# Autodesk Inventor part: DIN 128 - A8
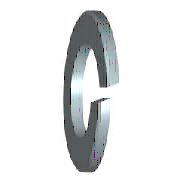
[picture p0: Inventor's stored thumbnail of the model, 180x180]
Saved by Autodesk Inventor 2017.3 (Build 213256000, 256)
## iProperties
Created: 2016-02
Part Number: DIN 128 - A8
Material: Acier, doux
Description: Rondelle élastique
Document SubType Name: Modeling
Standard: DIN 128
Designer: TJ
Standard Revision: 1994
Standards Organization: DIN
Language: fr-FR
Size Designation: A8
Categories: <MemberInstance><Categories><Category DisplayName="Visserie" InternalName="e4da775c-781d-43d5-af7c-5136215cf5a6" Mnemonic="FSTN"><Category DisplayName="Rondelle
Density: 7.85 g/cm^3
Appearance: Semi-poli
IsCustomPart: 0
Author: TJ
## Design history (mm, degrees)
sketch "Esquisse1"
  geometry: C1 r 7.4 at (0, 0); C2 r 4.25 at (0, 0); 1 further point
  constraints: 2 centre point, 2 coincident
  dimensions: "d0" = 8.5 diameter of C2 (= SD1); "d1" = 14.8 diameter of C1 (= SD2)
extrude "Corps" new body sketch "Esquisse1" distance "d2" = 1.6 (= SD); taper "d3" = 0 deg
sketch "Esquisse2"
  geometry: L1 (0, -4.25)-(0, 4.25) reference; L2 (1.6, 7.4)-(1.6, -7.4) reference; L3 (-1.2, 0)-(7.2, 0) reference; L4 (0, -0.32)-(1.6, 0.604); L5 (0, 0.32)-(1.6, 1.244)
  constraints: 4 end point, 4 point on line, 1 parallel
  dimensions: "d4" = 0.32 distance from line of L3 L4.start (= 0.2 x SD); "d5" = 0.32 distance from line of L3 L5.start (= 0.2 x SD); "d6" = 60 deg angle of L2 L4 (= FAWI)
extrude "Coupe" cut sketch "Esquisse2" stored distance "d7" = 1.6 (= SD); taper "d8" = 0 deg
workaxis "Work Axis1"
workplane "Work Plane1"
body "Solid1"
fillet "Congé" dims "d13" = 0.5 (= R)
other parameters: "SD1" = 8.5 [user parameter; used in 1 equation term], "SD2" = 14.8 [user parameter; used in 1 equation term], "SD" = 1.6 [user parameter; used in 4 equation terms], "FAWI" = 60 deg [user parameter; used in 1 equation term], "d9" = 0, "d10" = 0, "d11" = 0, "d12" = 0, "R" = 0.5 [user parameter; used in 1 equation term], "NND" = 8 [user parameter]
